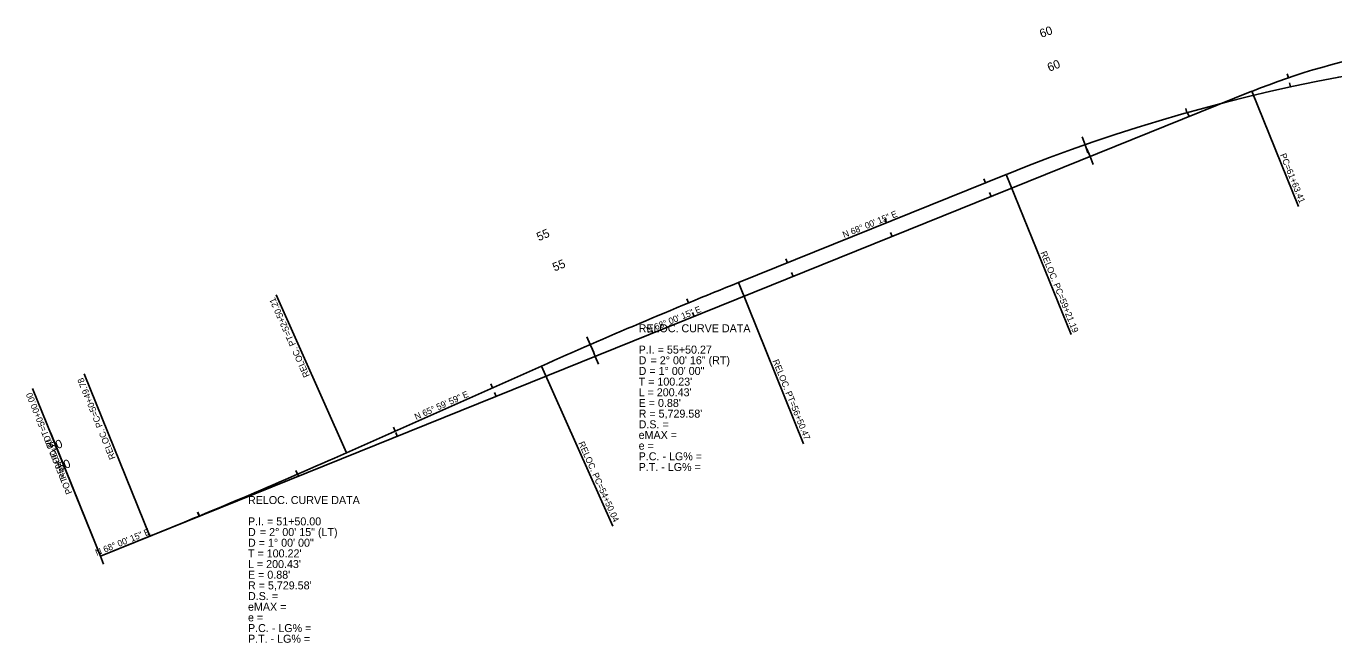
# Model space of a CAD drawing. Extents: x 1966701 to 1969292, y 1117367 to 1118089.
# Drawn here: x 1966701 to 1967926, y 1117367 to 1117945 of the extents above; entities that cross this region are included whole.
import ezdxf

# ---------------------------------------------------------------- set-up
doc = ezdxf.new("R2010")
doc.units = 0
for name, color, linetype in [('Level 1', 7, 'Continuous'), ('Level 19', 7, 'Continuous'), ('Level 2', 7, 'Continuous'), ('Level 3', 7, 'Continuous')]:
    doc.layers.add(name, color=color, linetype=linetype)

msp = doc.modelspace()

# ---------------------------------------------------------------- linework, layer by layer
at = {"layer": 'Level 1'}
for p, q in [((1967883.8, 1117896.6), (1967882.5, 1117900.4)), ((1966770.7, 1117448.1), (1967849.5, 1117883.9)), ((1967849.5, 1117883.9), (1967893.1, 1117775.9)), ((1967790.7, 1117860.1), (1967789.2, 1117863.8)), ((1967698, 1117822.7), (1967695, 1117830.1)), ((1967698, 1117822.7), (1967700.9, 1117815.2)), ((1967605.2, 1117785.2), (1967603.7, 1117788.9)), ((1967512.5, 1117747.7), (1967511, 1117751.5)), ((1967419.8, 1117710.3), (1967418.3, 1117714)), ((1967327.1, 1117672.8), (1967325.6, 1117676.5)), ((1967234.3, 1117635.4), (1967231.3, 1117642.8)), ((1967234.3, 1117635.4), (1967237.3, 1117628)), ((1967141.6, 1117597.9), (1967140.1, 1117601.6)), ((1967048.9, 1117560.5), (1967047.4, 1117564.2)), ((1966770.7, 1117448.1), (1966724.2, 1117563.4)), ((1966956.2, 1117523), (1966954.7, 1117526.7)), ((1966863.5, 1117485.6), (1966862, 1117489.3)), ((1966770.7, 1117448.1), (1966767.7, 1117455.5)), ((1966770.7, 1117448.1), (1966773.7, 1117440.7))]:
    msp.add_line(p, q, dxfattribs=at)
msp.add_arc((1968094.4, 1117277.5), 653.9, 87.7266, 111.9958, dxfattribs=at)
at = {"layer": 'Level 19'}
for p, q in [((1967885.6, 1117888), (1967884.7, 1117891.9)), ((1967788.6, 1117863.8), (1967787.5, 1117867.7)), ((1967693.2, 1117833.8), (1967690.6, 1117841.3)), ((1967693.2, 1117833.8), (1967695.8, 1117826.2)), ((1967368.4, 1117704.6), (1967619.4, 1117806)), ((1967599.8, 1117798.1), (1967598.3, 1117801.8)), ((1967507.1, 1117760.7), (1967505.6, 1117764.4)), ((1967414.4, 1117723.2), (1967412.9, 1117726.9)), ((1967321.7, 1117685.5), (1967320.2, 1117689.2)), ((1967229.7, 1117646.5), (1967226.5, 1117653.8)), ((1967229.7, 1117646.5), (1967232.9, 1117639.1)), ((1967001.4, 1117545.1), (1967183.9, 1117626.3)), ((1967138.2, 1117606), (1967136.6, 1117609.6)), ((1967046.9, 1117565.3), (1967045.2, 1117569)), ((1966955.4, 1117524.8), (1966953.8, 1117528.5)), ((1966863.4, 1117485.8), (1966861.8, 1117489.5)), ((1966770.7, 1117448.1), (1966816.9, 1117466.8)), ((1966770.7, 1117448.1), (1966767.7, 1117455.5)), ((1966770.7, 1117448.1), (1966773.7, 1117440.7))]:
    msp.add_line(p, q, dxfattribs=at)
for centre, radius, start, end in [((1968232.6, 1116288.2), 1637, 87.7266, 111.9958), ((1969514.4, 1112392.1), 5729.6, 111.99584, 114.00015), ((1964670.9, 1122779.3), 5729.6, 291.9959, 294.00015)]:
    msp.add_arc(centre, radius, start, end, dxfattribs=at)
at = {"layer": 'Level 3'}
for p, q in [((1967619.4, 1117806), (1967680.1, 1117655.8)), ((1967368.4, 1117704.6), (1967429.6, 1117553.3)), ((1967001.4, 1117545.1), (1966935.5, 1117693.1)), ((1967183.9, 1117626.3), (1967250.8, 1117476.2)), ((1966816.9, 1117466.8), (1966755.4, 1117619)), ((1966770.7, 1117448.1), (1966707.2, 1117605.4))]:
    msp.add_line(p, q, dxfattribs=at)

# ---------------------------------------------------------------- texts
at = {"layer": 'Level 1'}
for s, rotation, p in [('PC=61+63.41', 291.9958, (1967875.7, 1117824.3)), ('POT=50+00.00', 111.9958, (1966744.5, 1117507.6))]:
    msp.add_text(s, height=6, rotation=rotation, dxfattribs=at).set_placement(p)
at = {"layer": 'Level 19'}
for s, rotation, p in [('60', 19.2374, (1967652.3, 1117933.9)), ('55', 23.5006, (1967181.5, 1117743.3)), ('50', 21.9959, (1966725.1, 1117546.2))]:
    msp.add_text(s, height=8, rotation=rotation, dxfattribs=at).set_placement(p)
for s, p in [('RELOC. CURVE DATA', (1967275, 1117658)), ('P.I. = 55+50.27', (1967275, 1117638)), ('D', (1967275, 1117628)), ('D = 1%%d 00\' 00"', (1967275, 1117618)), ('    = 2%%d 00\' 16" (RT)', (1967275, 1117628)), ("T = 100.23'", (1967275, 1117608)), ("L = 200.43'", (1967275, 1117598)), ("E = 0.88'", (1967275, 1117588)), ("R = 5,729.58'", (1967275, 1117578)), ('eMAX = ', (1967275, 1117558)), ('D.S. = ', (1967275, 1117568)), ('e = ', (1967275, 1117548)), ('P.C. - LG% = ', (1967275, 1117538)), ('P.T. - LG% = ', (1967275, 1117528)), ('RELOC. CURVE DATA', (1966909, 1117497)), ('P.I. = 51+50.00', (1966909, 1117477)), ('D', (1966909, 1117467)), ('    = 2%%d 00\' 15" (LT)', (1966909, 1117467)), ("T = 100.22'", (1966909, 1117447)), ('D = 1%%d 00\' 00"', (1966909, 1117457)), ("L = 200.43'", (1966909, 1117437)), ("E = 0.88'", (1966909, 1117427)), ("R = 5,729.58'", (1966909, 1117417)), ('D.S. = ', (1966909, 1117407)), ('eMAX = ', (1966909, 1117397)), ('e = ', (1966909, 1117387)), ('P.C. - LG% = ', (1966909, 1117377)), ('P.T. - LG% = ', (1966909, 1117367))]:
    msp.add_text(s, height=7.5, dxfattribs=at).set_placement(p)
at = {"layer": 'Level 2'}
for s, height, p in [('60', 8, (1967659.8, 1117902.1)), ('55', 8, (1967196.2, 1117714.9)), ('N 68%%d 00\' 15" E', 6, (1967283.7, 1117656.9)), ('50', 8, (1966732.6, 1117527.6))]:
    msp.add_text(s, height=height, rotation=21.9958, dxfattribs=at).set_placement(p)
at = {"layer": 'Level 3'}
for s, rotation, p in [('N 68%%d 00\' 15" E', 21.9958, (1967467.5, 1117746.3)), ('RELOC. PC=59+21.19', 291.9958, (1967651.3, 1117732.6)), ('RELOC. PT=52+50.21', 114.0002, (1966967, 1117617.3)), ('RELOC. PT=56+50.47', 291.9958, (1967400.3, 1117631.2)), ('RELOC. PC=50+49.78', 111.9959, (1966785.1, 1117540.2)), ('RELOC. POT=50+00.00', 111.9959, (1966738.9, 1117521.5)), ('N 65%%d 59\' 59" E', 24.0002, (1967066.6, 1117575.7)), ('RELOC. PC=54+50.04', 294.0002, (1967218.3, 1117554.1)), ('N 68%%d 00\' 15" E', 21.9959, (1966767.4, 1117448.4))]:
    msp.add_text(s, height=6, rotation=rotation, dxfattribs=at).set_placement(p)

doc.saveas('drawing.dxf')
